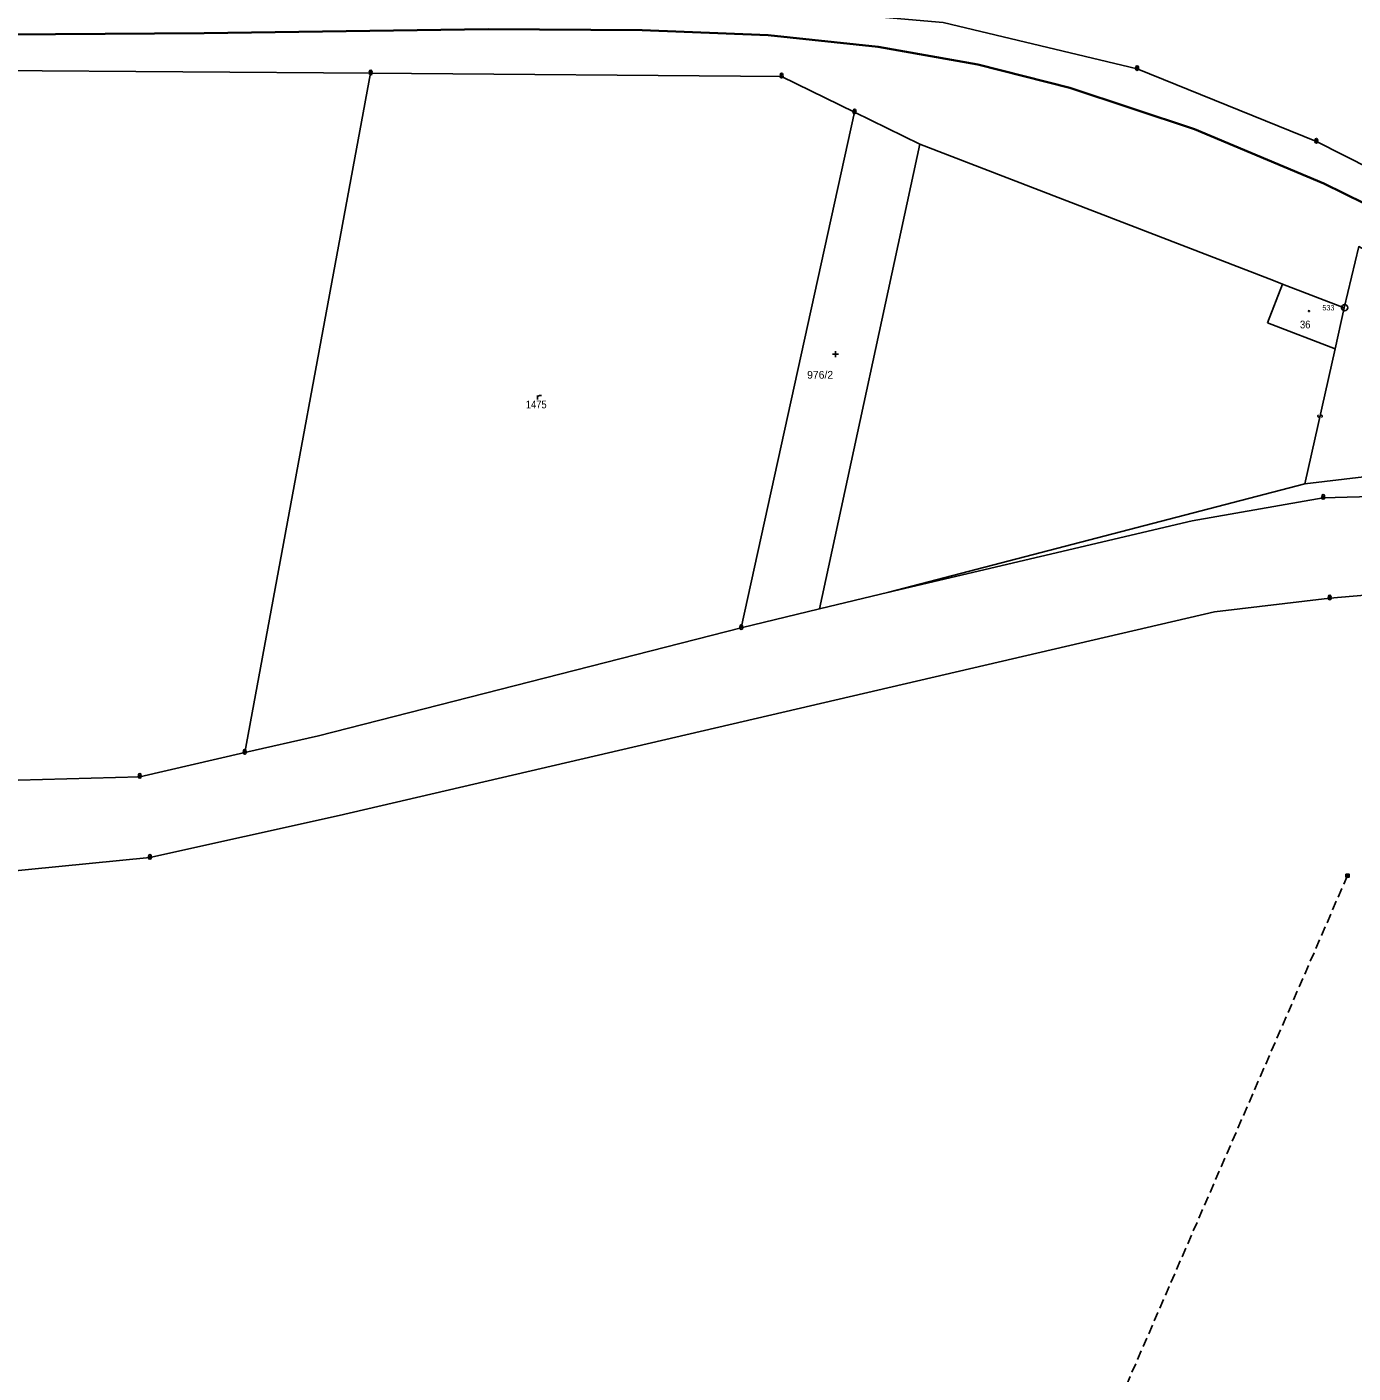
# Model space of a CAD drawing. Extents: x -871901 to -870967, y -1075952 to -1074892.
# Drawn here: x -871609.8 to -871439.3, y -1075441.5 to -1075268.5 of the extents above; entities that cross this region are included whole.
import ezdxf
from ezdxf.enums import TextEntityAlignment as Align

# ---------------------------------------------------------------- set-up
doc = ezdxf.new("R2010")
doc.units = 0
doc.header["$LTSCALE"] = 0.4
doc.linetypes.add('MEDIUM_DASHED', pattern=[4.5, 3, -1.5])
for name, color, linetype, lineweight in [('1', 7, 'Continuous', 25), ('10', 7, 'Continuous', 35), ('12', 7, 'MEDIUM_DASHED', 25), ('24', 7, 'Continuous', 25), ('25', 7, 'Continuous', 25), ('26', 7, 'Continuous', 25), ('4', 7, 'Continuous', 25)]:
    doc.layers.add(name, color=color, linetype=linetype, lineweight=lineweight)
for name, color, linetype in [('17', 7, 'Continuous'), ('18', 7, 'Continuous'), ('19', 7, 'Continuous')]:
    doc.layers.add(name, color=color, linetype=linetype)

msp = doc.modelspace()

# ---------------------------------------------------------------- linework, layer by layer
at = {"layer": '1'}
for p, q in [((-871565.58, -1075274.43), (-871581.77, -1075361.77)), ((-871517.94, -1075345.74), (-871503.38, -1075279.44)), ((-871503.38, -1075279.44), (-871495.01, -1075283.55)), ((-871507.87, -1075343.3), (-871495.01, -1075283.55)), ((-871495.01, -1075283.55), (-871449.54, -1075301.09)), ((-871450.3, -1075306.53), (-871448.37, -1075301.54)), ((-871450.3, -1075306.53), (-871441.59, -1075309.84)), ((-871445.51, -1075327.21), (-871394.16, -1075321.17)), ((-871498.97, -1075341.15), (-871445.51, -1075327.21)), ((-871459.98, -1075331.95), (-871443.14, -1075329)), ((-871443.14, -1075329), (-871416.95, -1075328.37)), ((-871498.97, -1075341.15), (-871459.98, -1075331.95)), ((-871507.87, -1075343.3), (-871498.97, -1075341.15)), ((-871581.77, -1075361.77), (-871572.27, -1075359.6))]:
    msp.add_line(p, q, dxfattribs=at)
for points in [[(-871846.94, -1075171.67), (-871815.83, -1075191.94), (-871796.55, -1075203.2), (-871765.31, -1075221.39), (-871734.8, -1075238.65), (-871721.92, -1075244.81), (-871706.47, -1075250.92), (-871674.71, -1075260.45), (-871646.68, -1075265.23), (-871608.79, -1075266.42), (-871553.79, -1075265.47), (-871523.09, -1075265.22), (-871491.97, -1075267.91), (-871467.05, -1075273.87), (-871444.01, -1075283.21), (-871377.38, -1075316.93)], [(-871565.58, -1075274.43), (-871613.89, -1075274.07), (-871646.86, -1075272.41), (-871670.8, -1075268.84)], [(-871503.38, -1075279.44), (-871512.76, -1075274.83), (-871565.58, -1075274.43)], [(-871441.59, -1075309.84), (-871440.45, -1075304.59), (-871438.58, -1075296.72), (-871394.16, -1075321.17)], [(-871449.54, -1075301.09), (-871448.37, -1075301.54), (-871440.45, -1075304.59)], [(-871377.92, -1075335.98), (-871384.74, -1075335.75), (-871415.81, -1075339.64), (-871442.3, -1075341.92), (-871457.12, -1075343.68), (-871569.63, -1075369.86), (-871593.96, -1075375.27), (-871613.49, -1075377.17), (-871630.54, -1075375.46), (-871654.44, -1075369.56), (-871683.36, -1075359.66)], [(-871572.27, -1075359.6), (-871517.94, -1075345.74), (-871507.87, -1075343.3)], [(-871627.46, -1075364.95), (-871610.89, -1075365.32), (-871595.26, -1075364.86), (-871581.77, -1075361.77)]]:
    msp.add_lwpolyline(points, dxfattribs=at)
at = {"layer": '10'}
msp.add_line((-871443.06, -1075288.59), (-871416.88, -1075301.49), dxfattribs=at)
msp.add_lwpolyline([(-871838.74, -1075182), (-871771.68, -1075221.29), (-871743.32, -1075237.24), (-871725.75, -1075246.25), (-871714.22, -1075251.23), (-871699.81, -1075256.65), (-871676.57, -1075263.06), (-871660.16, -1075266.31), (-871642.88, -1075268.42), (-871618.84, -1075269.48), (-871586.98, -1075269.26), (-871550.47, -1075268.77), (-871530.68, -1075268.88), (-871514.5, -1075269.55), (-871500.36, -1075271.03), (-871487.52, -1075273.3), (-871475.72, -1075276.29), (-871459.68, -1075281.62), (-871443.06, -1075288.59)], dxfattribs=at)
at = {"layer": '12'}
msp.add_lwpolyline([(-871440.02, -1075377.58), (-871476.16, -1075460.89), (-871517.14, -1075554.83)], dxfattribs=at)
at = {"layer": '24'}
for centre, radius in [((-871467.0495, -1075273.8695), 0.2005), ((-871467.0495, -1075273.8695), 0.00851), ((-871565.5795, -1075274.4295), 0.2005), ((-871565.5795, -1075274.4295), 0.00851), ((-871512.7595, -1075274.8295), 0.2005), ((-871512.7595, -1075274.8295), 0.00851), ((-871503.3795, -1075279.4395), 0.2005), ((-871503.3795, -1075279.4395), 0.00851), ((-871444.0095, -1075283.2095), 0.2005), ((-871444.0095, -1075283.2095), 0.00851), ((-871440.3895, -1075304.5795), 0.4005), ((-871440.3895, -1075304.5795), 0.0125), ((-871443.1395, -1075328.9995), 0.2005), ((-871443.1395, -1075328.9995), 0.00851), ((-871442.2995, -1075341.9195), 0.2005), ((-871442.2995, -1075341.9195), 0.00851), ((-871517.9395, -1075345.7395), 0.2005), ((-871517.9395, -1075345.7395), 0.00851), ((-871581.7695, -1075361.7695), 0.2005), ((-871581.7695, -1075361.7695), 0.00851), ((-871595.2595, -1075364.8595), 0.2005), ((-871595.2595, -1075364.8595), 0.00851), ((-871593.9595, -1075375.2695), 0.2005), ((-871593.9595, -1075375.2695), 0.00851)]:
    msp.add_circle(centre, radius, dxfattribs=at)
for centre in [(-871467.0498, -1075273.6436), (-871565.5798, -1075274.2036), (-871512.7598, -1075274.6036), (-871503.3798, -1075279.2136), (-871444.0098, -1075282.9836), (-871443.1398, -1075328.7736), (-871442.2998, -1075341.6936), (-871517.9398, -1075345.5136), (-871581.7698, -1075361.5436), (-871595.2598, -1075364.6336), (-871593.9598, -1075375.0436)]:
    msp.add_arc(centre, 0.1746, 328.19485, 209.95045, dxfattribs=at)
at = {"layer": '25'}
for p, q in [((-871505.83, -1075310.94), (-871505.83, -1075310.139)), ((-871506.23, -1075310.539), (-871505.429, -1075310.539)), ((-871544.12, -1075316.38), (-871544.12, -1075315.859))]:
    msp.add_line(p, q, dxfattribs=at)
msp.add_lwpolyline([(-871544.12, -1075316.023), (-871544.048, -1075315.952), (-871543.969, -1075315.907), (-871543.857, -1075315.877), (-871543.752, -1075315.858), (-871543.639, -1075315.851)], dxfattribs=at)
msp.add_circle((-871444.9595, -1075305.0095), 0.0705, dxfattribs=at)
for centre, radius, start, end in [((-871443.6931, -1075318.4859), 0.1471, 114.93559, 346.62832), ((-871443.4065, -1075318.554), 0.1474, 294.83169, 167.61021)]:
    msp.add_arc(centre, radius, start, end, dxfattribs=at)
at = {"layer": '26'}
for points in [[(-871440.22, -1075377.379), (-871439.819, -1075377.379), (-871439.819, -1075377.78), (-871440.22, -1075377.78)], [(-871440.14, -1075377.459), (-871439.899, -1075377.459), (-871439.899, -1075377.7), (-871440.14, -1075377.7)], [(-871440.06, -1075377.539), (-871439.979, -1075377.539), (-871439.979, -1075377.62), (-871440.06, -1075377.62)]]:
    msp.add_lwpolyline(points, close=True, dxfattribs=at)
at = {"layer": '4'}
msp.add_line((-871445.51, -1075327.21), (-871441.59, -1075309.84), dxfattribs=at)

# ---------------------------------------------------------------- texts
at = {"layer": '17', "width": 0.9}
msp.add_text('533', height=0.68, dxfattribs=at).set_placement((-871441.69, -1075304.92), align=Align.RIGHT)
at = {"layer": '18'}
msp.add_text('976/2', height=1, dxfattribs=at).set_placement((-871509.48, -1075313.7))
at = {"layer": '18', "width": 0.9}
msp.add_text('1475', height=1, dxfattribs=at).set_placement((-871545.64, -1075317.51))
at = {"layer": '19', "width": 0.9}
msp.add_text('36', height=1, dxfattribs=at).set_placement((-871446.12, -1075307.23))

doc.saveas('drawing.dxf')
